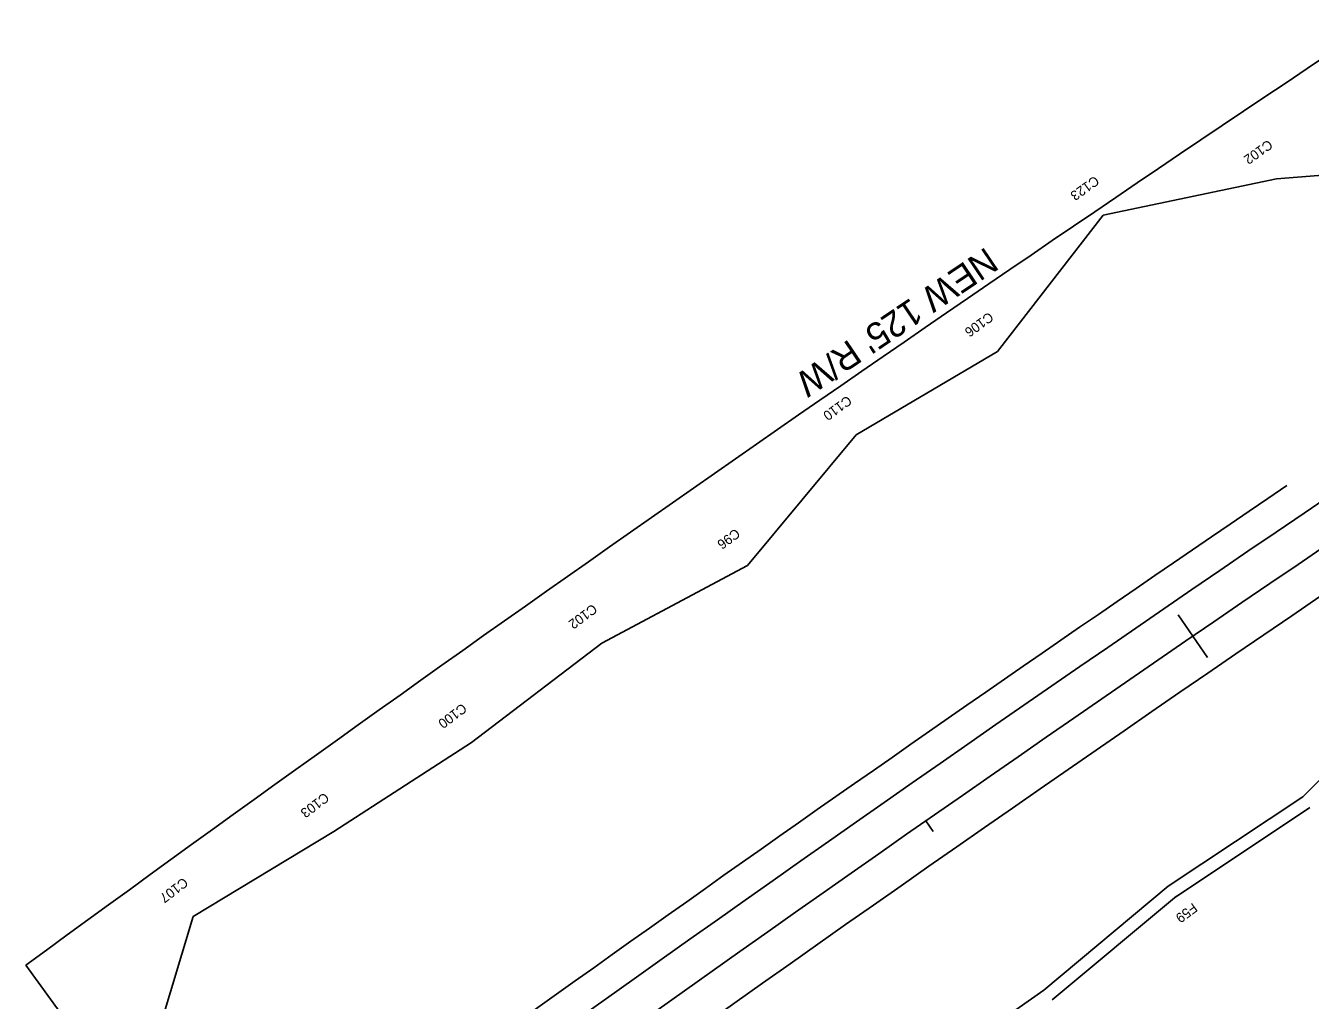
# Model space of a CAD drawing. Extents: x 1469024 to 1473560, y 1105695 to 1109739.
# Drawn here: x 1471083.5 to 1471479.1, y 1107815.4 to 1108115.5 of the extents above; entities that cross this region are included whole.
import ezdxf

# ---------------------------------------------------------------- set-up
doc = ezdxf.new("R2010")
doc.units = 0
for name, color, linetype in [('RD_HC_CL_Rel', 7, 'Continuous'), ('RD_HC_Data_Tic_Rel', 7, 'Continuous'), ('RD_PD_CstnLmt', 7, 'Continuous'), ('RD_PD_CstnLmt_TX', 7, 'Continuous'), ('RD_PD_DR_ErosCtrl', 7, 'Continuous'), ('RD_PD_Final_TrvlWay', 7, 'Continuous'), ('RD_PD_GR', 7, 'Continuous'), ('RD_PD_RW', 7, 'Continuous'), ('RD_PD_RW_TX', 7, 'Continuous')]:
    doc.layers.add(name, color=color, linetype=linetype)

msp = doc.modelspace()

# ---------------------------------------------------------------- linework, layer by layer
at = {"layer": 'RD_HC_CL_Rel'}
msp.add_arc((1477943.58, 1098441.09), 11500, 123.079489, 126.41418, dxfattribs=at)
at = {"layer": 'RD_HC_Data_Tic_Rel'}
for p, q in [((1471442.93, 1107927.48), (1471438.41, 1107934.08)), ((1471442.93, 1107927.48), (1471447.45, 1107920.88)), ((1471360.69, 1107870.59), (1471362.98, 1107867.31))]:
    msp.add_line(p, q, dxfattribs=at)
at = {"layer": 'RD_PD_CstnLmt'}
for p, q in [((1471526.3, 1108072.88), (1471468.75, 1108068.28)), ((1471468.75, 1108068.28), (1471415.33, 1108057.15)), ((1471415.33, 1108057.15), (1471382.82, 1108015.2)), ((1471382.82, 1108015.2), (1471339.24, 1107989.5)), ((1471339.24, 1107989.5), (1471305.78, 1107949.25)), ((1471305.78, 1107949.25), (1471260.92, 1107925.38)), ((1471260.92, 1107925.38), (1471220.79, 1107894.77)), ((1471512.43, 1107914.12), (1471476.8, 1107878.06)), ((1471220.79, 1107894.77), (1471178.42, 1107867.3)), ((1471476.8, 1107878.06), (1471435.38, 1107850.5)), ((1471178.42, 1107867.3), (1471135.06, 1107841.18)), ((1471435.38, 1107850.5), (1471397.03, 1107818.54)), ((1471135.06, 1107841.18), (1471116.88, 1107780.53)), ((1471397.03, 1107818.54), (1471356.39, 1107789.89))]:
    msp.add_line(p, q, dxfattribs=at)
at = {"layer": 'RD_PD_DR_ErosCtrl'}
for p, q in [((1471479.01, 1107874.73), (1471437.6, 1107847.17)), ((1471437.94, 1107847.42), (1471399.59, 1107815.47))]:
    msp.add_line(p, q, dxfattribs=at)
at = {"layer": 'RD_PD_Final_TrvlWay'}
for radius in [11512, 11488]:
    msp.add_arc((1477943.58, 1098441.09), radius, 123.079489, 126.41418, dxfattribs=at)
at = {"layer": 'RD_PD_GR'}
msp.add_arc((1477943.58, 1098441.09), 11522, 124.172166, 126.408649, dxfattribs=at)
at = {"layer": 'RD_PD_RW'}
msp.add_line((1471113.01, 1107785.82), (1471083.51, 1107826.19), dxfattribs=at)
msp.add_arc((1477943.58, 1098441.09), 11625, 123.673947, 126.165068, dxfattribs=at)

# ---------------------------------------------------------------- texts
at = {"layer": 'RD_PD_CstnLmt_TX'}
for s, rotation, p in [('C102', 215.4345, (1471466.17, 1108080.56)), ('C123', 215.6836, (1471412.73, 1108069.44)), ('C106', 215.9327, (1471380.16, 1108027.47)), ('C110', 216.1818, (1471336.53, 1108001.76)), ('C96', 216.431, (1471302.1, 1107960.83)), ('C102', 216.6801, (1471258.08, 1107937.6)), ('C100', 216.9292, (1471217.92, 1107907)), ('C103', 217.1783, (1471175.5, 1107879.51)), ('C107', 217.4274, (1471132.06, 1107853.36)), ('F59', 216.1818, (1471442.95, 1107845.5))]:
    msp.add_text(s, height=3, rotation=rotation, dxfattribs=at).set_placement(p)
at = {"layer": 'RD_PD_RW_TX'}
msp.add_text("NEW 125' R/W", height=8, rotation=214.0223, dxfattribs=at).set_placement((1471379.26, 1108047.53))

doc.saveas('drawing.dxf')
